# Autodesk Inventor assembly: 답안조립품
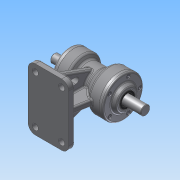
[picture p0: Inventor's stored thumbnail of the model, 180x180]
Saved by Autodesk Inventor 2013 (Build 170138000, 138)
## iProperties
Created: 2015-08
Part Number: 답안조립품
Document SubType Name: Assembly
Designer: Administrator
Author: Administrator
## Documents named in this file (10)
- C:\Users\Administrator\Desktop\450806V1016\답안조립품.iam
- C:\Users\Administrator\Desktop\450806V1016\본체.ipt
- C:\Users\Administrator\Desktop\450806V1016\M4x0.5.ipt
- C:\Users\Administrator\Desktop\450806V1016\뒤커버.ipt
- C:\Users\Administrator\Desktop\450806V1016\베어링 6203.ipt
- C:\Users\Administrator\Desktop\450806V1016\베어링 6205.ipt
- C:\Users\Administrator\Desktop\450806V1016\앞커버.ipt
- C:\Users\Administrator\Desktop\450806V1016\오일실 .ipt
- 오일실 .ipt
- C:\Users\Administrator\Desktop\450806V1016\축.ipt
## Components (10 placed, 1 different names)
1. M4x0.5:1
2. M4x0.5:3
3. M4x0.5:4
4. M4x0.5:5
5. M4x0.5:6
6. M4x0.5:2
7. M4x0.5:7
8. M4x0.5:8
9. M4x0.5:9
10. M4x0.5:10
